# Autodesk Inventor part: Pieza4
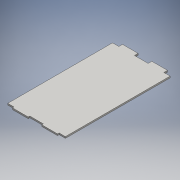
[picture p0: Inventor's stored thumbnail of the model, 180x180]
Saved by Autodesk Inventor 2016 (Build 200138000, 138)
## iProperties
Created: 2016-06
Part Number: Pieza4
Material: Genérico
Document SubType Name: Modeling
Designer: adm
Density: 1 g/cm^3
Appearance: Valor por defecto
Author: adm
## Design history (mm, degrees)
sketch "Boceto1"
  geometry: L1 (-55, -100)-(-55, 100); L2 (55, 100)-(55, -100); L3 (55, -100)-(-55, 100); L4 (-55, -100)-(55, 100); L5 (-13, 100)-(-13, 107); L6 (-13, 107)-(-43, 107); L7 (-43, 107)-(-43, 100); L8 (13, 100)-(13, 107); L9 (13, 107)-(43, 107); L10 (43, 107)-(43, 100); L11 (-13, -100)-(-13, -103); L12 (-13, -103)-(-43, -103); L13 (-43, -103)-(-43, -100); L14 (43, -103)-(43, -100); L15 (13, -103)-(43, -103); L16 (13, -100)-(13, -103); L17 (55, -100)-(43, -100); L18 (43, 100)-(55, 100); L19 (-55, 100)-(-43, 100); L20 (-13, 100)-(13, 100); L21 (13, -100)-(-13, -100); L22 (-43, -100)-(-55, -100); 2 further points
  constraints: 44 end point, 12 parallel, 8 horizontal alignment, 3 horizontal, 3 midpoint, 3 perpendicular, 3 vertical alignment
  dimensions: "d0" = 200 distance of L2.start L2.end; "d1" = 110 distance of L2.end L1.start; "d2" = 12 distance between parallel lines of L1 L7; "d3" = 30 distance of L5.end L6.end; "d6" = 12 distance between parallel lines of L1 L13; "d7" = 30 distance of L11.end L12.end; "d12" = 7 distance of L5.start L5.end; "d13" = 3 distance of L11.start L11.end; "d14" = 30 distance of L15.start L14.start; "d15" = 3 distance of L14.start L14.end; "d16" = 12 distance between parallel lines of L2 L14; "d17" = 7 distance of L9.end L10.end; "d18" = 7 distance of L8.start L8.end; "d20" = 26 distance of L16.start L11.start; "d21" = 30 distance of L8.end L9.end
extrude "Extrusión1" new body sketch "Boceto1" distance "d8" = 3; taper "d9" = 0 deg
node "Sólido1"
other parameters: "d4" = 7
